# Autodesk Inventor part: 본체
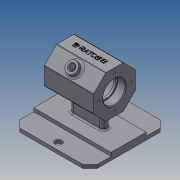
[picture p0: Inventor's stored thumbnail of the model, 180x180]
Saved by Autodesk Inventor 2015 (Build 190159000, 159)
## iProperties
Created: 2018-06
Part Number: 본체
Material: 일반
Document SubType Name: Modeling
Designer: 임동건
Density: 1 g/cm^3
Appearance: 기본값
Author: 임동건
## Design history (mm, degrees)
sketch "스케치1"
  geometry: L1 (-55, 55)-(55, 55); L2 (55, 55)-(55, -55); L3 (55, -55)-(-55, -55); L4 (-55, -55)-(-55, 55); L5 (-55, 25)-(55, 25); L6 (55, 25)-(55, -25); L7 (55, -25)-(-55, -25); L8 (-55, -25)-(-55, 25); L9 (-19, 0)-(19, 0); L10 (-19, -5)-(19, -5); L11 (19, 5)-(-19, 5); C1 r 5 at (0, 45); C2 r 5 at (0, -45); A1 r 5 centre (-19, 0) between (-19, 5) and (-19, -5); A2 r 5 centre (19, 0) between (19, -5) and (19, 5); 5 further points
  constraints: 24 end point, 5 parallel, 4 centre point, 4 midpoint, 4 point on circle, 4 tangent, 3 horizontal, 3 vertical alignment, 2 horizontal alignment, 2 perpendicular, 2 point on line, 1 coincident
  dimensions: "d0" = 110 distance between parallel lines of L3 L1; "d1" = 110 distance between parallel lines of L2 L4; "d3" = 30 distance between parallel lines of L5 L1; "d4" = 10 diameter of C1; "d5" = 10 diameter of C2; "d6" = 10 distance from line of L1 C1.centre; "d7" = 10 distance from line of L3 C2.centre; "d8" = 5 radius of A2; "d9" = 38 distance of L9.end L9.start
extrude "돌출1" new body sketch "스케치1" distance "d10" = 5; taper "d11" = 0 deg
extrude "돌출2" join sketch "스케치1" distance "d12" = 10; taper "d13" = 0 deg
chamfer "모따기1" distance "d14" = 10; stored, may be unused: second distance "d15" = 2, angle "d16" = 45 deg
extrude "돌출3" join sketch "스케치1" distance "d17" = 32; taper "d18" = 0 deg
sketch "스케치2"
  geometry: L1 (-30, 49.574)-(-30, 74.426); L2 (-30, 74.426)-(-12.426, 92); L3 (-12.426, 92)-(12.426, 92); L4 (12.426, 92)-(30, 74.426); L5 (30, 74.426)-(30, 49.574); L6 (30, 49.574)-(12.426, 32); L7 (12.426, 32)-(-12.426, 32); L8 (-12.426, 32)-(-30, 49.574); L9 (-45, 0)-(45, 0) reference; C1 r 25 at (0, 62); 4 further points
  constraints: 16 end point, 3 vertical alignment, 2 midpoint, 1 centre point, 1 coincident, 17 other
  dimensions: "d19" = 62 distance of point (0, 0) point (0, 62); "d20" = 92 distance between parallel lines of L9 L3; "d22" = 50 diameter of C1
extrude "돌출4" join sketch "스케치2" stored distance "d23" = 70; taper "d24" = 0 deg
extrude "돌출5" cut sketch "스케치2" stored distance "d25" = 40; taper "d26" = 0 deg
sketch "스케치3"
  geometry: L1 (49.574, -30)-(74.426, -30) reference; L2 (74.426, -30)-(92, -12.426) reference; L3 (92, -12.426)-(92, 12.426) reference; L4 (92, 12.426)-(74.426, 30) reference; L5 (74.426, 30)-(49.574, 30) reference; L6 (49.574, 30)-(32, 12.426) reference; L7 (32, 12.426)-(32, -12.426) reference; L8 (32, -12.426)-(49.574, -30) reference; L9 (0, 45)-(0, -45) reference; C1 r 16 at (62, 0); C2 r 14 at (62, 0); 2 further points
  constraints: 2 centre point, 1 horizontal alignment, 1 midpoint
  dimensions: "d27" = 32 diameter of C1; "d28" = 62 distance from line of L9 C1.centre; "d29" = 28 diameter of C2
  node "투영된 루프1"
extrude "돌출6" cut sketch "스케치3" distance "d30" = 12; taper "d31" = 0 deg
extrude "돌출7" cut sketch "스케치3" stored distance "d32" = 12; taper "d33" = 0 deg
sketch "스케치4"
  geometry: L1 (0, 0)-(0, 24.853) reference; C1 r 8 at (35, 12.426); 2 further points
  constraints: 1 centre point, 1 horizontal alignment, 1 midpoint, 1 vertical alignment
  dimensions: "d34" = 16 diameter of C1
extrude "돌출8" join sketch "스케치4" distance "d35" = 7; taper "d36" = 0 deg
hole "구멍1" diameter "d39" = 8; stored, may be unused: countersink angle "d43" = 90 deg, drill point angle "d45" = 0 deg; dims "d37" = 10, "d38" = 10, "d40" = 6, "d41" = 8, "d42" = 2, "d44" = 15
fillet "모깎기1" dims "d46" = 1
fillet "모깎기2" dims "d47" = 3
fillet "모깎기5" dims "d50" = 2
fillet "모깎기6" dims "d51" = 0.3
sketch "스케치5"
  geometry: L1 (0, 45)-(0, -45) reference; L2 (32, 12.012)-(32, -12.012) reference; L3 (32.293, -12.719)-(49.281, -29.707) reference; L4 (49.988, -30)-(74.012, -30) reference; L5 (74.719, -29.707)-(91.707, -12.719) reference; L6 (92, -12.012)-(92, 12.012) reference; L7 (91.707, 12.719)-(74.719, 29.707) reference; L8 (74.012, 30)-(49.988, 30) reference; L9 (49.281, 29.707)-(32.293, 12.719) reference; C1 r 16 at (62, 0) reference; A1 r 1 centre (33, 12.012) between (32.293, 12.719) and (32, 12.012) reference; A2 r 1 centre (33, -12.012) between (32, -12.012) and (32.293, -12.719) reference; A3 r 1 centre (49.988, -29) between (49.281, -29.707) and (49.988, -30) reference; A4 r 1 centre (74.012, -29) between (74.012, -30) and (74.719, -29.707) reference; A5 r 1 centre (91, -12.012) between (91.707, -12.719) and (92, -12.012) reference; A6 r 1 centre (91, 12.012) between (92, 12.012) and (91.707, 12.719) reference; A7 r 1 centre (74.012, 29) between (74.719, 29.707) and (74.012, 30) reference; A8 r 1 centre (49.988, 29) between (49.988, 30) and (49.281, 29.707) reference; 3 further points
  constraints: 1 horizontal alignment, 1 midpoint
  dimensions: "d52" = 23 distance of C1.centre point (85, 0)
hole "구멍2" sketch "스케치5" at (85, 0) diameter "d53" = 3.242; stored, may be unused: countersink angle "d57" = 90 deg, drill point angle "d59" = 120 deg; dims "d54" = 8, "d55" = 8, "d56" = 2, "d58" = 10
sketch "스케치6"
  geometry: L1 (10.908, -8.635)-(59.092, -8.635); L2 (59.092, -8.635)-(59.092, -15.389); L3 (59.092, -15.389)-(10.908, -15.389); L4 (10.908, -15.389)-(10.908, -8.635); L5 (70, 0)-(70, -24.024) reference; 5 further points
  constraints: 3 midpoint, 1 coincident, 1 horizontal alignment, 1 vertical alignment, 2 other
feature "엠보싱1" sketch "스케치6" dims "d0" = 110, "d1" = 110, "d3" = 30, "d4" = 10, "d5" = 10, "d6" = 10, "d7" = 10, "d63" = 0.5, "d64" = 0
chamfer "모따기2" distance "d65" = 1; stored, may be unused: second distance "d66" = 2, angle "d67" = 45 deg
chamfer "모따기3" distance "d68" = 1; stored, may be unused: second distance "d69" = 2, angle "d70" = 45 deg
fillet "모깎기7" dims "d71" = 3
node "솔리드1"
mirror "대칭1"
pattern_circular "원형 패턴1" dims angle "d61" = 360 deg
mirror "대칭2"
node "투영된 루프2"
